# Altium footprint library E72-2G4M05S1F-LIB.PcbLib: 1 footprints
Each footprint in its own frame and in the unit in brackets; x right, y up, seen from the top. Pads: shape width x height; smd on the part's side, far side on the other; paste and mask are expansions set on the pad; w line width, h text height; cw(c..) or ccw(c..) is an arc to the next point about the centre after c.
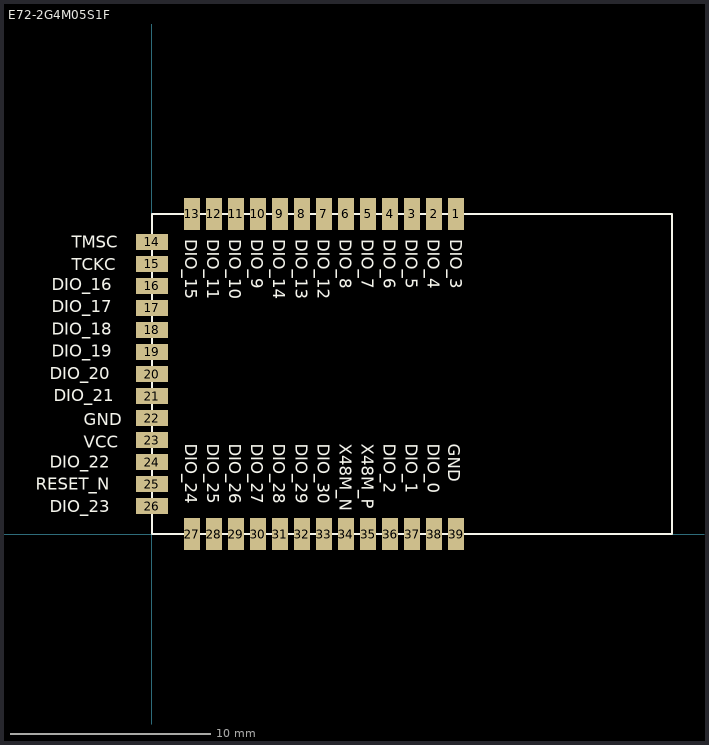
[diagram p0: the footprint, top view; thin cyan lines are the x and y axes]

## E72-2G4M05S1F [mm]
pads (39):
  rect 0.8x1.6 smd: 1(15.2,16) 2(14.1,16) 3(13,16) 4(11.9,16) 5(10.8,16) 6(9.7,16) 7(8.6,16) 8(7.5,16) 9(6.4,16) 10(5.3,16) 11(4.2,16) 12(3.1,16) 13(2,16) 27(2,0) 28(3.1,0) 29(4.2,0) 30(5.3,0) 31(6.4,0) 32(7.5,0) 33(8.6,0) 34(9.7,0) 35(10.8,0) 36(11.9,0) 37(13,0) 38(14.1,0) 39(15.2,0)
  rect 1.6x0.8 smd: 14(0,14.6) 15(0,13.5) 16(0,12.4) 17(0,11.3) 18(0,10.2) 19(0,9.1) 20(0,8) 21(0,6.9) 22(0,5.8) 23(0,4.7) 24(0,3.6) 25(0,2.5) 26(0,1.4)
Top Overlay:
  lines w0.1: 0,0 0,16 26,16 26,0 0,0
  text "DIO_23" at -5.1,1.1 h0.6
  text "DIO_22" at -5.1,3.317 h0.6
  text "VCC" at -3.401,4.325 h0.6
  text "DIO_21" at -4.9,6.642 h0.6
  text "DIO_19" at -5,8.858 h0.6
  text "DIO_17" at -5,11.075 h0.6
  text "TCKC" at -4,13.192 h0.6
  text "GND" at -3.401,5.433 h0.6
  text "DIO_20" at -5.1,7.75 h0.6
  text "TMSC" at -4,14.3 h0.6
  text "DIO_16" at -5,12.183 h0.6
  text "DIO_18" at -5,9.967 h0.6
  text "RESET_N" at -5.8,2.208 h0.6
  text "DIO_11" at 2.764,14.734 h0.6
  text "DIO_9" at 4.97,14.734 h0.6
  text "DIO_13" at 7.177,14.734 h0.6
  text "DIO_8" at 9.383,14.734 h0.6
  text "DIO_7" at 10.487,14.734 h0.6
  text "DIO_5" at 12.693,14.734 h0.6
  text "DIO_3" at 14.9,14.734 h0.6
  text "DIO_14" at 6.074,14.734 h0.6
  text "DIO_10" at 3.867,14.734 h0.6
  text "DIO_15" at 1.66,14.734 h0.6
  text "DIO_6" at 11.59,14.734 h0.6
  text "DIO_12" at 8.28,14.734 h0.6
  text "DIO_4" at 13.797,14.734 h0.6
  text "DIO_25" at 2.764,4.518 h0.6
  text "DIO_27" at 4.97,4.518 h0.6
  text "DIO_29" at 7.177,4.518 h0.6
  text "X48M_N" at 9.383,4.518 h0.6
  text "X48M_P" at 10.487,4.518 h0.6
  text "DIO_1" at 12.693,4.518 h0.6
  text "GND" at 14.8,4.518 h0.6
  text "DIO_24" at 1.66,4.518 h0.6
  text "DIO_26" at 3.867,4.518 h0.6
  text "DIO_28" at 6.074,4.518 h0.6
  text "DIO_0" at 13.797,4.518 h0.6
  text "DIO_30" at 8.28,4.518 h0.6
  text "DIO_2" at 11.59,4.518 h0.6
